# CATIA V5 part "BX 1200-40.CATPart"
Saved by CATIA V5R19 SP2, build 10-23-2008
Part number: BX 1200-40
Bounding box of the stored display mesh (mm): x -59.975 to 59.975, y -59.975 to 59.975, z 0 to 220
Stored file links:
  C:\Users\Bora\Desktop\3D Katı model\BX serisi\BX 1200\BX 1200-40.CATPart
  C:\Program Files\Dassault Systemes\B19\intel_a\reffiles\standard\MetricThickPitch.txt
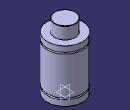
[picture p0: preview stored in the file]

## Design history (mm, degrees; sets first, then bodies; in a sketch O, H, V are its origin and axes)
Body1 (main body)
  Sketch1 on yz-plane, origin (0, 0, 0), H (0, 1, 0), V (0, 0, 1)
    point P2 (60, 20)
    line L1 (60, 20) -> (60, 0)
    point P3 (60, 25)
    point P4 (60, 155)
    line L2 (60, 155) -> (60, 25)
    point P6 (35, 219)
    arc A1 centre (34, 219) radius 1 from (35, 219) to (34, 220) ccw
    point P8 (35, 219)
    line L3 (35, 219) -> (35, 179)
    point P9 (60, 160)
    line L4 (60, 179) -> (60, 160)
    point P11 (60, 20)
    point P12 (60, 25)
    arc A2 centre (60, 22.5) radius 2.5 from (60, 25) to (60, 20) ccw
    point P13 (60, 155)
    point P14 (60, 160)
    arc A3 centre (60, 157.5) radius 2.5 from (60, 160) to (60, 155) ccw
    line L5 (34, 220) -> (0, 220)
    point P15 (0, 220)
    line L6 (35, 179) -> (60, 179)
    line L7 (60, 0) -> (0, 0)
    tangency: L5 A1
    coincidence: P15 V, P2 P11, P3 P12, P4 P13, P6 P8, P9 P14
    horizontal: L6 H, L7 H
  Shaft1: profile Sketch1, axis Sketch1.V, angle 360
  Sketch2 on face of Shaft1 from Sketch1.L7, origin (0, 0, 0), H (1, 0, 0), V (0, -1, 0)
    point P1 (32.5, 0)
    distance P1 V = 32.5
  Hole1: placed by Sketch2, at (32.5, 0, 0) direction (0, 0, 1), diameter 8.376, depth 10, threaded "M10", thread diameter 10, thread depth 10, pitch 1.5
  CircPattern1: of Hole1, instances 4, angular step 90, axis from xy-plane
